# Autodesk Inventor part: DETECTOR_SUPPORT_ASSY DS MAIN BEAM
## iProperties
Shininess: 64.0
Length Units: 11272
Angle Units: 11279
Time Units: 11290
Mass Units: 11286
Length Display Precision: 3
Angle Display Precision: 2
Compacted: True
Part Number: DETECTOR_SUPPORT_ASSY DS MAIN BEAM
Document SubType Name: Modeling
Created: 2004-08
Designer: John Blackburn
Material: MILD_STEEL
Manufacturer: Standard
Standards Organization: Custom
Density: 0.0
Volumn: 0.0
Area: 0.0
PropertySet Name: Model Information
Control State: 0
Master: False
Checked Out: False
Author: John Blackburn
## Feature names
1. ExtrusionMidplane1
2. ExtrusionThru1
3. ExtrusionThru2
4. ExtrusionThru3
5. ExtrusionThru4
6. ExtrusionThru5
7. ExtrusionThru6
8. ExtrusionThru7
9. ExtrusionBlind1
10. ExtrusionBlind2
